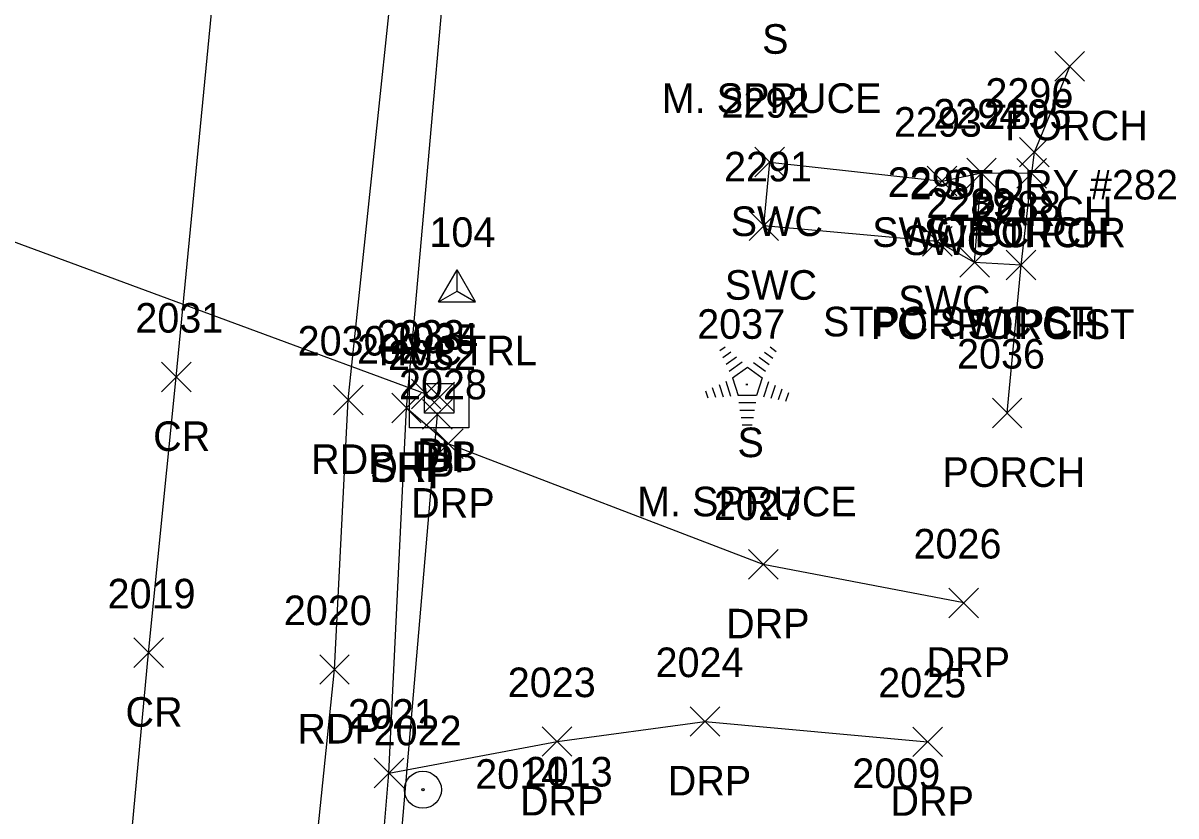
# Model space of a CAD drawing. Extents: x 1653908 to 1654393, y 539913 to 544256.
# Drawn here: x 1654091.7 to 1654169.7, y 541966.6 to 542020.2 of the extents above; entities that cross this region are included whole.
import ezdxf

# ---------------------------------------------------------------- set-up
doc = ezdxf.new("R2010")
doc.units = 0
for name, color, linetype in [('C_A', 7, 'Continuous'), ('C_I', 7, 'Continuous'), ('CPSM', 7, 'Continuous'), ('D_A', 7, 'Continuous'), ('D_I', 7, 'Continuous'), ('D_TIC', 7, 'Continuous'), ('DCP', 7, 'Continuous'), ('DS', 7, 'Continuous'), ('L_A', 7, 'Continuous'), ('L_C', 7, 'Continuous'), ('L_I', 7, 'Continuous'), ('L_TIC', 7, 'Continuous'), ('LBF', 7, 'Continuous'), ('LTC', 7, 'Continuous'), ('P_A', 7, 'Continuous'), ('P_I', 7, 'Continuous'), ('P_TIC', 7, 'Continuous'), ('PET', 7, 'Continuous'), ('PRC', 7, 'Continuous'), ('PSP', 7, 'Continuous'), ('R_A', 7, 'Continuous'), ('R_I', 7, 'Continuous'), ('R_TIC', 7, 'Continuous'), ('RDP', 7, 'Continuous'), ('RGP', 7, 'Continuous'), ('RSW', 7, 'Continuous')]:
    doc.layers.add(name, color=color, linetype=linetype)

msp = doc.modelspace()

# ---------------------------------------------------------------- linework, layer by layer
at = {"layer": 'CPSM'}
for p, q in [((1654119.824, 542001.387), (1654121.074, 542003.552)), ((1654122.324, 542001.387), (1654121.074, 542003.552)), ((1654121.075, 542002.109), (1654121.074, 542003.552)), ((1654119.824, 542001.387), (1654121.075, 542002.109)), ((1654121.075, 542002.109), (1654121.075, 542002.109)), ((1654121.075, 542002.109), (1654122.324, 542001.387)), ((1654119.824, 542001.387), (1654122.324, 542001.387))]:
    msp.add_line(p, q, dxfattribs=at)
at = {"layer": 'D_TIC'}
for points in [[(1654117.981, 541994.162), (1654119.981, 541996.162)], [(1654119.981, 541994.162), (1654117.981, 541996.162)], [(1654118.891, 541993.96), (1654120.891, 541995.96)], [(1654120.891, 541993.96), (1654118.891, 541995.96)], [(1654118.744, 541992.79), (1654120.744, 541994.79)], [(1654120.744, 541992.79), (1654118.744, 541994.79)]]:
    msp.add_lwpolyline(points, dxfattribs=at)
at = {"layer": 'DCP'}
for points in [[(1654118.981, 541995.162), (1654084.537, 542007.871)], [(1654106.161, 541835.083), (1654119.744, 541993.79)]]:
    msp.add_lwpolyline(points, dxfattribs=at)
at = {"layer": 'DS'}
for p, q in [((1654117.861, 541996.872), (1654121.861, 541996.872)), ((1654117.861, 541992.872), (1654117.861, 541996.872)), ((1654121.861, 541996.872), (1654121.861, 541992.872)), ((1654118.861, 541993.872), (1654118.861, 541995.872)), ((1654118.861, 541995.872), (1654120.861, 541995.872)), ((1654120.861, 541995.872), (1654120.861, 541993.872)), ((1654119.866, 541994.874), (1654119.866, 541994.874)), ((1654119.866, 541994.874), (1654119.866, 541994.874)), ((1654120.861, 541993.872), (1654118.861, 541993.872)), ((1654121.861, 541992.872), (1654117.861, 541992.872))]:
    msp.add_line(p, q, dxfattribs=at)
at = {"layer": 'L_TIC'}
for points in [[(1654161.509, 542016.316), (1654163.509, 542018.316)], [(1654163.509, 542016.316), (1654161.509, 542018.316)], [(1654159.119, 542010.515), (1654161.119, 542012.515)], [(1654161.119, 542010.515), (1654159.119, 542012.515)], [(1654155.541, 542009.111), (1654157.541, 542011.111)], [(1654157.541, 542009.111), (1654155.541, 542011.111)], [(1654158.934, 542009.087), (1654160.934, 542011.087)], [(1654160.934, 542009.087), (1654158.934, 542011.087)], [(1654158.934, 542009.087), (1654160.934, 542011.087)], [(1654160.934, 542009.087), (1654158.934, 542011.087)], [(1654155.078, 542003.062), (1654157.078, 542005.062)], [(1654157.078, 542003.062), (1654155.078, 542005.062)], [(1654158.216, 542002.884), (1654160.216, 542004.884)], [(1654160.216, 542002.884), (1654158.216, 542004.884)], [(1654158.216, 542002.884), (1654160.216, 542004.884)], [(1654160.216, 542002.884), (1654158.216, 542004.884)], [(1654157.277, 541992.886), (1654159.277, 541994.886)], [(1654159.277, 541992.886), (1654157.277, 541994.886)]]:
    msp.add_lwpolyline(points, dxfattribs=at)
at = {"layer": 'LBF'}
for points in [[(1654158.277, 541993.886), (1654159.216, 542003.884), (1654159.934, 542010.087), (1654160.119, 542011.515), (1654162.509, 542017.316)], [(1654159.216, 542003.884), (1654156.078, 542004.062), (1654156.541, 542010.111), (1654159.934, 542010.087)]]:
    msp.add_lwpolyline(points, dxfattribs=at)
at = {"layer": 'LTC'}
for p, q in [((1654138.845, 541998.106), (1654139.2, 541998.363)), ((1654139.055, 541997.641), (1654139.584, 541998.025)), ((1654139.264, 541997.175), (1654139.968, 541997.686)), ((1654141.502, 541997.65), (1654142.181, 541997.156)), ((1654141.872, 541997.998), (1654142.422, 541997.599)), ((1654142.244, 541998.346), (1654142.663, 541998.042)), ((1654139.474, 541996.709), (1654140.352, 541997.347)), ((1654139.699, 541996.254), (1654140.71, 541996.988)), ((1654140.71, 541996.988), (1654141.707, 541996.263)), ((1654141.13, 541997.301), (1654141.94, 541996.713)), ((1654139.699, 541996.254), (1654140.086, 541995.061)), ((1654141.707, 541996.263), (1654141.316, 541995.061)), ((1654137.878, 541995.385), (1654138.03, 541994.917)), ((1654138.333, 541995.602), (1654138.545, 541994.95)), ((1654138.789, 541995.818), (1654139.06, 541994.983)), ((1654139.244, 541996.035), (1654139.575, 541995.016)), ((1654142.145, 541995.993), (1654141.807, 541994.953)), ((1654142.589, 541995.742), (1654142.302, 541994.858)), ((1654143.034, 541995.492), (1654142.797, 541994.763)), ((1654141.316, 541995.061), (1654140.086, 541995.061)), ((1654141.278, 541994.561), (1654140.133, 541994.561)), ((1654143.478, 541995.242), (1654143.292, 541994.668)), ((1654141.194, 541994.061), (1654140.206, 541994.061)), ((1654141.11, 541993.561), (1654140.279, 541993.561)), ((1654141.027, 541993.061), (1654140.352, 541993.061))]:
    msp.add_line(p, q, dxfattribs=at)
at = {"layer": 'P_TIC'}
for points in [[(1654101.082, 541995.315), (1654103.082, 541997.315)], [(1654103.082, 541995.315), (1654101.082, 541997.315)], [(1654112.712, 541993.764), (1654114.712, 541995.764)], [(1654114.712, 541993.764), (1654112.712, 541995.764)], [(1654116.65, 541993.217), (1654118.65, 541995.217)], [(1654118.65, 541993.217), (1654116.65, 541995.217)], [(1654099.212, 541976.673), (1654101.212, 541978.673)], [(1654101.212, 541976.673), (1654099.212, 541978.673)], [(1654111.78, 541975.541), (1654113.78, 541977.541)], [(1654113.78, 541975.541), (1654111.78, 541977.541)], [(1654115.462, 541968.541), (1654117.462, 541970.541)], [(1654117.462, 541968.541), (1654115.462, 541970.541)]]:
    msp.add_lwpolyline(points, dxfattribs=at)
at = {"layer": 'PET'}
msp.add_lwpolyline([(1654079.776, 541659.551), (1654080.091, 541663.585), (1654084.434, 541705.035), (1654088.467, 541726.588), (1654090.823, 541750.421), (1654095.245, 541793.922), (1654098.735, 541834.906), (1654102.668, 541873.549), (1654106.19, 541915.359), (1654108.801, 541937.78), (1654112.78, 541976.541), (1654113.712, 541994.764), (1654118.507, 542040.261), (1654122.37, 542081.456), (1654125.512, 542120.567), (1654128.858, 542154.493), (1654132.07, 542197.521), (1654136.387, 542232.744)], dxfattribs=at)
at = {"layer": 'PRC'}
msp.add_lwpolyline([(1654071.378, 541669.623), (1654074.689, 541707.082), (1654077.078, 541730.589), (1654080.001, 541762.219), (1654083.127, 541795.122), (1654087.252, 541836.363), (1654090.634, 541873.535), (1654094.478, 541915.806), (1654096.589, 541938.824), (1654100.212, 541977.673), (1654102.082, 541996.315), (1654106.328, 542040.19), (1654109.98, 542082.612), (1654113.749, 542122.62), (1654117.046, 542159.879), (1654120.869, 542199.278), (1654124.055, 542234.043)], dxfattribs=at)
at = {"layer": 'PSP'}
msp.add_lwpolyline([(1654094.458, 541721.214), (1654096.104, 541749.586), (1654101.261, 541800.15), (1654104.956, 541834.324), (1654108.508, 541872.884), (1654110.153, 541890.734), (1654111.767, 541915.009), (1654113.741, 541937.092), (1654116.462, 541969.541), (1654117.65, 541994.217), (1654121.735, 542040.282), (1654126.757, 542081.182), (1654129.731, 542120.034), (1654133.658, 542152.736), (1654138.064, 542196.396), (1654141.276, 542231.97)], dxfattribs=at)
at = {"layer": 'R_TIC'}
for points in [[(1654141.216, 542009.845), (1654143.216, 542011.845)], [(1654143.216, 542009.845), (1654141.216, 542011.845)], [(1654155.541, 542009.111), (1654157.541, 542011.111)], [(1654157.541, 542009.111), (1654155.541, 542011.111)], [(1654152.876, 542008.559), (1654154.876, 542010.559)], [(1654154.876, 542008.559), (1654152.876, 542010.559)], [(1654140.822, 542005.538), (1654142.822, 542007.538)], [(1654142.822, 542005.538), (1654140.822, 542007.538)], [(1654152.549, 542004.487), (1654154.549, 542006.487)], [(1654154.549, 542004.487), (1654152.549, 542006.487)], [(1654155.078, 542003.062), (1654157.078, 542005.062)], [(1654157.078, 542003.062), (1654155.078, 542005.062)], [(1654116.65, 541993.217), (1654118.65, 541995.217)], [(1654118.65, 541993.217), (1654116.65, 541995.217)], [(1654119.48, 541990.807), (1654121.48, 541992.807)], [(1654121.48, 541990.807), (1654119.48, 541992.807)], [(1654140.778, 541982.648), (1654142.778, 541984.648)], [(1654142.778, 541982.648), (1654140.778, 541984.648)], [(1654154.337, 541980.047), (1654156.337, 541982.047)], [(1654156.337, 541980.047), (1654154.337, 541982.047)], [(1654136.833, 541972.028), (1654138.833, 541974.028)], [(1654138.833, 541972.028), (1654136.833, 541974.028)], [(1654126.837, 541970.675), (1654128.837, 541972.675)], [(1654128.837, 541970.675), (1654126.837, 541972.675)], [(1654151.896, 541970.655), (1654153.896, 541972.655)], [(1654153.896, 541970.655), (1654151.896, 541972.655)], [(1654115.462, 541968.541), (1654117.462, 541970.541)], [(1654117.462, 541968.541), (1654115.462, 541970.541)]]:
    msp.add_lwpolyline(points, dxfattribs=at)
at = {"layer": 'RDP'}
for points in [[(1654155.337, 541981.047), (1654141.778, 541983.648), (1654120.48, 541991.807), (1654117.65, 541994.217)], [(1654116.462, 541969.541), (1654127.837, 541971.675), (1654137.833, 541973.028), (1654152.896, 541971.655)]]:
    msp.add_lwpolyline(points, dxfattribs=at)
at = {"layer": 'RGP'}
msp.add_line((1654118.762, 541968.418), (1654118.762, 541968.418), dxfattribs=at)
for radius in [1.25, 0.0833]:
    msp.add_circle((1654118.762, 541968.418), radius, dxfattribs=at)
at = {"layer": 'RSW'}
msp.add_lwpolyline([(1654156.078, 542004.062), (1654153.549, 542005.487), (1654141.822, 542006.538), (1654142.216, 542010.845), (1654153.876, 542009.559), (1654156.541, 542010.111)], dxfattribs=at)

# ---------------------------------------------------------------- texts
at = {"layer": 'C_A'}
msp.add_text('HVCTRL', height=2, dxfattribs=at).set_placement((1654115.768, 541997.109))
at = {"layer": 'C_I'}
msp.add_text('104', height=2, dxfattribs=at).set_placement((1654119.201, 542005.109))
at = {"layer": 'D_A'}
for s, p in [('DIB', (1654117.994, 541989.96)), ('P', (1654118.359, 541990.162)), ('DI', (1654118.921, 541989.874)), ('P', (1654119.122, 541988.79))]:
    msp.add_text(s, height=2, dxfattribs=at).set_placement(p)
at = {"layer": 'D_I'}
for s, p in [('2033', (1654115.642, 541998.162)), ('2034', (1654116.553, 541997.96)), ('2035', (1654116.528, 541997.874)), ('2032', (1654116.406, 541996.79))]:
    msp.add_text(s, height=2, dxfattribs=at).set_placement(p)
at = {"layer": 'L_A'}
for s, p in [('S', (1654141.702, 542018.166)), ('PORCH', (1654158.131, 542012.316)), ('PORCH', (1654155.741, 542006.515)), ('SWC STPC', (1654149.148, 542005.111)), ('STPC POR', (1654152.635, 542005.087)), ('PORCH', (1654155.556, 542005.087)), ('STPC SWC ST', (1654145.818, 541999.062)), ('POR STPC ST', (1654149.051, 541998.884)), ('PORCH', (1654154.838, 541998.884)), ('S', (1654140.036, 541990.898)), ('PORCH', (1654153.899, 541988.886))]:
    msp.add_text(s, height=2, dxfattribs=at).set_placement(p)
at = {"layer": 'L_C'}
for s, p in [('M. SPRUCE', (1654134.915, 542014.166)), ('2 STORY #282', (1654151.69, 542008.316)), ('M. SPRUCE', (1654133.249, 541986.898))]:
    msp.add_text(s, height=2, dxfattribs=at).set_placement(p)
at = {"layer": 'L_I'}
for s, p in [('2296', (1654156.804, 542014.515)), ('2294', (1654153.282, 542013.111)), ('2295', (1654156.674, 542013.087)), ('2295', (1654156.674, 542013.087)), ('2289', (1654152.81, 542007.062)), ('2288', (1654155.957, 542006.884)), ('2288', (1654155.957, 542006.884)), ('2037', (1654137.312, 541998.898)), ('2036', (1654154.884, 541996.886)), ('2014', (1654122.301, 541968.48)), ('2014', (1654122.301, 541968.48)), ('2013', (1654125.642, 541968.634)), ('2009', (1654147.803, 541968.532))]:
    msp.add_text(s, height=2, dxfattribs=at).set_placement(p)
at = {"layer": 'LTC'}
msp.add_text('.', height=1.037, rotation=270, dxfattribs=at).set_placement((1654140.593, 541996.002))
at = {"layer": 'P_A'}
for s, p in [('CR', (1654100.515, 541991.315)), ('RDP', (1654111.2, 541989.764)), ('SHP', (1654115.186, 541989.217)), ('CR', (1654098.645, 541972.673)), ('RDP', (1654110.269, 541971.541))]:
    msp.add_text(s, height=2, dxfattribs=at).set_placement(p)
at = {"layer": 'P_I'}
for s, p in [('2031', (1654099.31, 541999.315)), ('2030', (1654110.287, 541997.764)), ('2029', (1654114.304, 541997.217)), ('2019', (1654097.433, 541980.673)), ('2020', (1654109.355, 541979.541)), ('2021', (1654113.69, 541972.541))]:
    msp.add_text(s, height=2, dxfattribs=at).set_placement(p)
at = {"layer": 'R_A'}
for s, p in [('SWC', (1654139.578, 542005.845)), ('SWC STPC', (1654149.148, 542005.111)), ('SWC', (1654151.238, 542004.559)), ('SWC', (1654139.184, 542001.538)), ('SWC', (1654150.911, 542000.487)), ('STPC SWC ST', (1654145.818, 541999.062)), ('DRP', (1654115.138, 541989.217)), ('DRP', (1654117.968, 541986.807)), ('DRP', (1654139.266, 541978.648)), ('DRP', (1654152.825, 541976.047)), ('DRP', (1654135.321, 541968.028)), ('DRP', (1654125.325, 541966.675)), ('DRP', (1654150.384, 541966.655))]:
    msp.add_text(s, height=2, dxfattribs=at).set_placement(p)
at = {"layer": 'R_I'}
for s, p in [('2292', (1654138.956, 542013.845)), ('2294', (1654153.282, 542013.111)), ('2293', (1654150.616, 542012.559)), ('2291', (1654139.129, 542009.538)), ('2290', (1654150.202, 542008.487)), ('2289', (1654152.81, 542007.062)), ('2029', (1654114.304, 541997.217)), ('2028', (1654117.142, 541994.807)), ('2027', (1654138.44, 541986.648)), ('2026', (1654151.943, 541984.047)), ('2024', (1654134.495, 541976.028)), ('2023', (1654124.499, 541974.675)), ('2025', (1654149.557, 541974.655)), ('2021', (1654113.69, 541972.541)), ('2022', (1654115.424, 541971.418))]:
    msp.add_text(s, height=2, dxfattribs=at).set_placement(p)

doc.saveas('drawing.dxf')
